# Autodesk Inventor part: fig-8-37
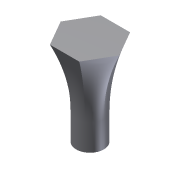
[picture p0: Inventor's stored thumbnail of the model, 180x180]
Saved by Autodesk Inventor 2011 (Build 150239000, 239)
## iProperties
Created: 2004-05
Part Number: fig-8-37
Document SubType Name: Modeling
Designer: CADCIM Technologies
Manufacturer: Standard
Standards Organization: Custom
Density: 1 g/cm^3
Author: CADCIM Technologies
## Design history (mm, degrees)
sketch "Sketch1"
  geometry: C1 r 16.344 at (0, 0)
  constraints: 1 centre point
extrude "Extrusion1" new body sketch "Sketch1" distance "d0" = 30.75; taper "d1" = 0 deg
workplane "Work Plane1"
sketch "Sketch2"
  geometry: L1 (34.788, 0)-(17.394, -30.128); L2 (17.394, -30.128)-(-17.394, -30.128); L3 (-17.394, -30.128)-(-34.788, 0); L4 (-34.788, 0)-(-17.394, 30.128); L5 (-17.394, 30.128)-(17.394, 30.128); L6 (17.394, 30.128)-(34.788, 0); 2 further points
  constraints: 12 end point, 1 coincident, 12 other
loft "Loft2" sketch "Sketch2" dims "d8" = 90 deg, "d9" = 0, "d10" = 90 deg, "d11" = 10
  node "Edges2"
body "Solid1"
other parameters: "d2" = 75
